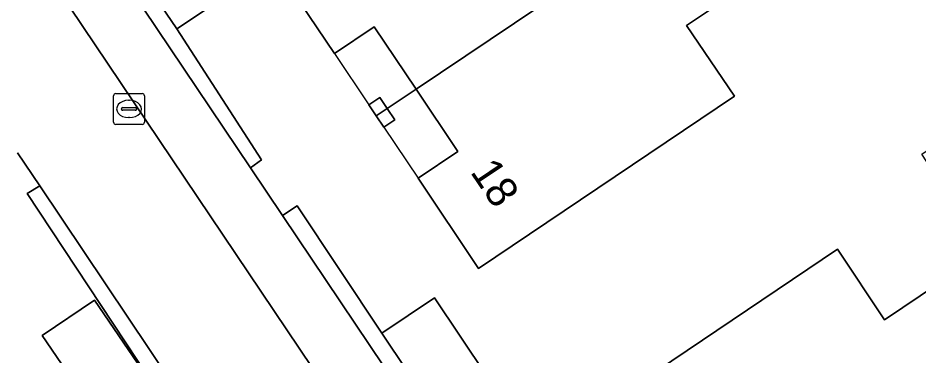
# Model space of a CAD drawing. Extents: x 158793 to 159888, y 384317 to 385256.
# Drawn here: x 158979.96 to 159009.12, y 384716.28 to 384727.22 of the extents above; entities that cross this region are included whole.
import ezdxf

# ---------------------------------------------------------------- set-up
doc = ezdxf.new("R2010")
doc.units = 0
for name, color, linetype in [('IMGEO_Erf', 7, 'Continuous'), ('IMGEO_Groenvoorziening', 7, 'Continuous'), ('IMGEO_Haag', 7, 'Continuous'), ('IMGEO_Kolk', 7, 'Continuous'), ('IMGEO_Pand', 7, 'Continuous'), ('IMGEO_Pand_nummerreeks', 7, 'Continuous'), ('IMGEO_Pand_overbouw', 7, 'Continuous'), ('IMGEO_Rijbaan_lokaal_open', 7, 'Continuous'), ('IMGEO_Voetpad_open', 7, 'Continuous')]:
    doc.layers.add(name, color=color, linetype=linetype)

msp = doc.modelspace()

# ---------------------------------------------------------------- linework, layer by layer
at = {"layer": 'IMGEO_Erf'}
for points in [[(159001.599, 384726.98), (159003.147, 384724.692), (158994.867, 384719.112), (158992.908, 384722.031), (158994.197, 384722.896), (158992.843, 384724.915), (158991.489, 384726.935), (158990.206, 384726.066), (158988.253, 384728.972), (158991.72, 384731.305), (158990.929, 384732.482), (158995.765, 384735.737), (158998.096, 384732.273), (158999.83, 384733.44), (159001.601, 384730.81), (159003.371, 384728.179)], [(158992.152, 384723.924), (158991.799, 384723.688), (158991.557, 384724.049), (158991.318, 384724.405), (158991.671, 384724.642), (158991.909, 384724.287)], [(159011.528, 384715.977), (159013.301, 384713.335), (159011.561, 384712.166), (159013.892, 384708.694), (159009.071, 384705.463), (159008.293, 384706.652), (159004.8, 384704.312), (159002.853, 384707.221), (159004.134, 384708.069), (159002.777, 384710.103), (159001.438, 384712.108), (159000.155, 384711.252), (158998.21, 384714.157), (159006.484, 384719.734), (159008.008, 384717.448), (159009.754, 384718.619)], [(158982.438, 384718.084), (158984.149, 384715.574), (158982.457, 384714.421), (158980.744, 384716.937)]]:
    msp.add_lwpolyline(points, close=True, dxfattribs=at)
for points in [[(158986.805, 384728.01), (158985.105, 384726.868), (158987.846, 384722.625), (158987.486, 384722.366), (158988.524, 384720.821), (158988.999, 384721.135), (158991.733, 384717.014), (158993.435, 384718.158), (158995.121, 384715.647), (158996.807, 384713.136), (158995.108, 384711.994), (158997.914, 384707.861), (158997.443, 384707.544), (158998.6, 384705.821), (158999.082, 384706.142), (159001.672, 384702.175), (159003.382, 384703.329), (159005.088, 384700.795), (159017.999, 384709.332), (159009.213, 384722.809), (159010.167, 384723.465), (159023.158, 384732.172)], [(158971.722, 384707.173), (158984.222, 384715.527), (158980.257, 384721.539), (158980.664, 384721.786), (158979.947, 384722.856)]]:
    msp.add_lwpolyline(points, dxfattribs=at)
at = {"layer": 'IMGEO_Groenvoorziening'}
for points in [[(158985.105, 384726.868), (158983.392, 384729.383), (158985.085, 384730.536), (158998.381, 384739.491), (159000.089, 384740.621), (158999.813, 384741.052), (158983.341, 384730.006), (158983.146, 384728.827), (158987.486, 384722.366), (158987.846, 384722.625)], [(158980.664, 384721.786), (158980.257, 384721.539), (158984.222, 384715.527), (158971.722, 384707.173), (158972.017, 384706.723), (158972.264, 384706.889), (158982.666, 384713.882), (158984.939, 384715.41)], [(158993.421, 384714.504), (158991.733, 384717.014), (158988.999, 384721.135), (158988.524, 384720.821), (158997.443, 384707.544), (158997.914, 384707.861), (158995.108, 384711.994)]]:
    msp.add_lwpolyline(points, close=True, dxfattribs=at)
at = {"layer": 'IMGEO_Haag'}
for points in [[(158998.381, 384739.491), (159000.089, 384740.621), (158999.813, 384741.052), (158983.341, 384730.006), (158983.146, 384728.827), (158987.486, 384722.366), (158987.846, 384722.625), (158985.105, 384726.868), (158983.392, 384729.383), (158985.085, 384730.536)], [(158980.664, 384721.786), (158980.257, 384721.539), (158984.222, 384715.527), (158971.722, 384707.173), (158972.017, 384706.723), (158972.264, 384706.889), (158982.666, 384713.882), (158984.939, 384715.41)], [(158993.421, 384714.504), (158991.733, 384717.014), (158988.999, 384721.135), (158988.524, 384720.821), (158997.443, 384707.544), (158997.914, 384707.861), (158995.108, 384711.994)]]:
    msp.add_lwpolyline(points, close=True, dxfattribs=at)
at = {"layer": 'IMGEO_Kolk'}
for p, q in [((158983.053, 384723.848), (158983.053, 384724.7)), ((158983.128, 384724.774), (158983.98, 384724.774)), ((158984.054, 384724.7), (158984.054, 384723.848)), ((158983.541, 384724.554), (158983.566, 384724.554)), ((158983.312, 384724.268), (158983.312, 384724.28)), ((158983.75, 384724.231), (158983.352, 384724.231)), ((158983.355, 384724.317), (158983.753, 384724.317)), ((158983.796, 384724.28), (158983.796, 384724.268)), ((158983.98, 384723.774), (158983.128, 384723.774)), ((158983.564, 384723.994), (158983.539, 384723.994))]:
    msp.add_line(p, q, dxfattribs=at)
for points in [[(158983.053, 384723.848), (158983.053, 384724.7)], [(158983.128, 384724.774), (158983.98, 384724.774)], [(158984.054, 384724.7), (158984.054, 384723.848)], [(158983.98, 384723.774), (158983.128, 384723.774)]]:
    msp.add_lwpolyline(points, dxfattribs=at)
for centre, radius, start, end in [((158983.13, 384724.698), 0.0765, 91.552, 178.448), ((158983.13, 384724.698), 0.0765, 91.552, 178.448), ((158983.978, 384724.698), 0.0765, 1.552, 88.448), ((158983.978, 384724.698), 0.0765, 1.552, 88.448), ((158983.352, 384724.277), 0.0403, 85.8775, 175.7526), ((158983.349, 384724.267), 0.0366, 178.938, 274.7102), ((158983.753, 384724.274), 0.043, 264.8664, 352.4533), ((158983.757, 384724.279), 0.0386, 1.7309, 96.639), ((158983.13, 384723.85), 0.0765, 181.552, 268.448), ((158983.13, 384723.85), 0.0765, 181.552, 268.448), ((158983.978, 384723.85), 0.0765, 271.552, 358.448), ((158983.978, 384723.85), 0.0765, 271.552, 358.448)]:
    msp.add_arc(centre, radius, start, end, dxfattribs=at)
for centre, major_axis, ratio, start_param, end_param in [((158983.54, 384724.274), (-0.387, 0.002), 0.722429, 4.712389, 7.853982), ((158983.565, 384724.274), (-0.39, 0.002), 0.717154, 1.570796, 4.712389)]:
    msp.add_ellipse(centre, major_axis=major_axis, ratio=ratio, start_param=start_param, end_param=end_param, dxfattribs=at)
at = {"layer": 'IMGEO_Pand'}
for points in [[(159001.601, 384730.81), (158999.83, 384733.44), (158998.096, 384732.273), (158995.765, 384735.737), (158990.929, 384732.482), (158991.72, 384731.305), (158988.253, 384728.972), (158990.206, 384726.066), (158991.489, 384726.935), (158992.843, 384724.915)], [(159001.599, 384726.98), (159003.371, 384728.179), (159001.601, 384730.81), (158992.843, 384724.915), (158994.197, 384722.896), (158992.908, 384722.031), (158994.867, 384719.112), (159003.147, 384724.692)], [(158983.392, 384729.383), (158985.105, 384726.868), (158986.805, 384728.01), (158985.085, 384730.536)], [(158991.909, 384724.287), (158991.671, 384724.642), (158991.318, 384724.405), (158991.557, 384724.049)], [(158991.909, 384724.287), (158991.557, 384724.049), (158991.799, 384723.688), (158992.152, 384723.924)], [(159011.528, 384715.977), (159009.754, 384718.619), (159008.008, 384717.448), (159006.484, 384719.734), (158998.21, 384714.157), (159000.155, 384711.252), (159001.438, 384712.108), (159002.777, 384710.103)], [(158980.744, 384716.937), (158982.457, 384714.421), (158984.149, 384715.574), (158982.438, 384718.084)], [(158991.733, 384717.014), (158993.421, 384714.504), (158995.121, 384715.647), (158993.435, 384718.158)]]:
    msp.add_lwpolyline(points, close=True, dxfattribs=at)
at = {"layer": 'IMGEO_Pand_overbouw'}
for points in [[(158991.318, 384724.405), (158991.557, 384724.049), (158991.909, 384724.287), (158992.843, 384724.915), (158991.489, 384726.935), (158990.206, 384726.066)], [(158992.843, 384724.915), (158991.909, 384724.287), (158991.557, 384724.049), (158991.799, 384723.688), (158992.908, 384722.031), (158994.197, 384722.896)]]:
    msp.add_lwpolyline(points, close=True, dxfattribs=at)
at = {"layer": 'IMGEO_Rijbaan_lokaal_open'}
for points in [[(159076.098, 384700.8), (159064.041, 384692.712), (159060.67, 384690.454), (159040.186, 384676.652), (159023.424, 384665.376), (159015.48, 384677.168), (159007.469, 384689.118), (159004.736, 384693.195), (158992.379, 384711.59), (158979.975, 384730.054)], [(158979.947, 384722.856), (158980.664, 384721.786), (158984.939, 384715.41), (158987.736, 384711.239), (158985.469, 384709.698), (158975.08, 384702.746)]]:
    msp.add_lwpolyline(points, dxfattribs=at)
at = {"layer": 'IMGEO_Voetpad_open'}
msp.add_lwpolyline([(159007.494, 384746.203), (159015.957, 384751.878), (159018.325, 384753.477), (159017.243, 384755.079), (159004.006, 384746.223), (158979.975, 384730.054), (158992.379, 384711.59), (159004.736, 384693.195), (159006.349, 384694.266), (159006.073, 384694.696), (159003.248, 384698.902), (158998.6, 384705.821), (158997.443, 384707.544), (158988.524, 384720.821), (158987.486, 384722.366), (158983.146, 384728.827), (158983.341, 384730.006), (158999.813, 384741.052), (159000.598, 384741.578), (159006.317, 384745.413)], close=True, dxfattribs=at)

# ---------------------------------------------------------------- texts
at = {"layer": 'IMGEO_Pand_nummerreeks'}
msp.add_text('18', height=1, rotation=303.8673, dxfattribs=at).set_placement((158994.576, 384722.237))

doc.saveas('drawing.dxf')
